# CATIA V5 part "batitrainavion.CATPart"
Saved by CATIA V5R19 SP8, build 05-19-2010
Part number: batitrainavion
Bounding box of the stored display mesh (mm): x -40 to 80, y -120 to 220, z -110 to 100
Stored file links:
  C:\Users\rcousturie\Desktop\EU_thinkMotion\iao\IAO_MMS_Groupe1\flamrini\Lamrini_projet_IAO2011\Lamrini_projet_IAO2011\projet_iao_traindatterrissage\projet_iao_traindatterrissage\batitrainavion.CATPart
  C:\Users\rcousturie\Desktop\EU_thinkMotion\iao\IAO_MMS_Groupe1\flamrini\Lamrini_projet_IAO2011\Lamrini_projet_IAO2011\projet_iao_traindatterrissage\projet_iao_traindatterrissage\trainavion.CATProduct
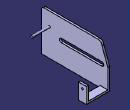
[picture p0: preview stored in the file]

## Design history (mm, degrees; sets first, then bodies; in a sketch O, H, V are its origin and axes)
Set1
  Sketch1 on yz-plane, origin (0, 0, 0), H (0, 1, 0), V (0, 0, 1)
    line L1 (-110, 100) -> (170, 100)
    arc A1 centre (170, 80) radius 20 from (170, 100) to (190, 80) cw
    line L2 (190, 80) -> (220, 0)
    line L3 (220, 0) -> (220, -110)
    line L4 (220, -110) -> (-120, -110)
    line L5 (-120, -110) -> (-120, 90)
    arc A2 centre (-110, 90) radius 10 from (-120, 90) to (-110, 100) cw
    horizontal: L1 H, L4 H
    tangency: A1 L1, A2 L1, A2 L5
    vertical: L3 V, L5 V
Set2
  Point1 "PointA": linked copy from another document
  Line1 "axeFbis": linked copy from another document
Body1 (main body)
  Pad1: profile Sketch1, direction (-1, 0, 0), length 40, opposite side length -30
  Sketch2 on start face of Pad1, origin (-30, 0, 0), H (0, 1, 0), V (0, 0, 1)
    circle A1 centre (-80, 30) radius 5
    point P1 (-80, 30)
    reference projected point E1 (-80, 30) from Point1
    radius A1 = 5
    coincidence: P1 E1
  Pad2: profile Sketch2, direction (1, 0, 0), length 90
  Sketch3 on face of Pad1 from Sketch1.L4, origin (0, 0, -110), H (1, 0, 0), V (0, -1, 0)
    line L1 (-40, -220) -> (80, -220)
    line L2 (80, -220) -> (80, -180)
    line L3 (80, -180) -> (-40, -180)
    line L4 (-40, -180) -> (-40, -220)
    reference projected line E1 (-40, 120) -> (-40, -220) from edge [end face of Pad1 | face of Pad1 from Sketch1.L4]
    reference projected line E2 (-30, -220) -> (-40, -220) from edge [face of Pad1 from Sketch1.L4 | face of Pad1 from Sketch1.L3]
    distance L3 L1 = 40
    horizontal: L1 H, L3 H
    vertical: L2 V, L4 V
    coincidence: L4 E1, L1 E2
  Pad3: profile Sketch3, direction (0, 0, 1), length 10
  Sketch4 on face of Pad3 from Sketch3.L2, origin (80, 0, 0), H (0, 1, 0), V (0, 0, 1)
    line L1 (180, -110) -> (220, -110)
    line L2 (220, -110) -> (220, -30)
    line L3 (220, -30) -> (180, -30)
    line L4 (180, -30) -> (180, -110)
    reference projected line E1 (220, -110) -> (180, -110) from edge [face of Pad3 from Sketch3.L2 | start face of Pad3]
    reference projected line E2 (180, -110) -> (180, -100) from edge [face of Pad3 from Sketch3.L2 | face of Pad3 from Sketch3.L3]
    reference projected line E3 (220, -110) -> (220, -100) from edge [face of Pad3 from Sketch3.L1 | face of Pad3 from Sketch3.L2]
    horizontal: L1 H, L3 H
    vertical: L2 V, L4 V
    coincidence: L1 E1, L4 E2, E3 L2
  Pad4: profile Sketch4, direction (-1, 0, 0), length 10
  Sketch5 on face of Pad4, origin (80, 200, -50), H (0, 1, 0), V (0, 0, 1)
    point P1 (0, 0)
  Hole1: placed by Sketch5, at (80, 200, -50) direction (-1, 0, 0), diameter 10, up to end face of Pad4
  Sketch6 on start face of Pad1, origin (-30, 0, 0), H (0, 1, 0), V (0, 0, 1)
    line L1 (-20, 10) -> (190, 10)
    arc A1 centre (190, 0) radius 10 from (190, 10) to (190, -10) cw
    line L2 (190, -10) -> (-20, -10)
    arc A2 centre (-20, 0) radius 10 from (-20, -10) to (-20, 10) cw
    horizontal: L1 H
    tangency: A1 L1, L2 A1, A2 L1, A2 L2
  Pocket1: profile Sketch6, direction (-1, 0, 0), through (limit type 3)
  Sketch7 on start face of Pad1, origin (-30, 0, 0), H (0, 1, 0), V (0, 0, 1)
